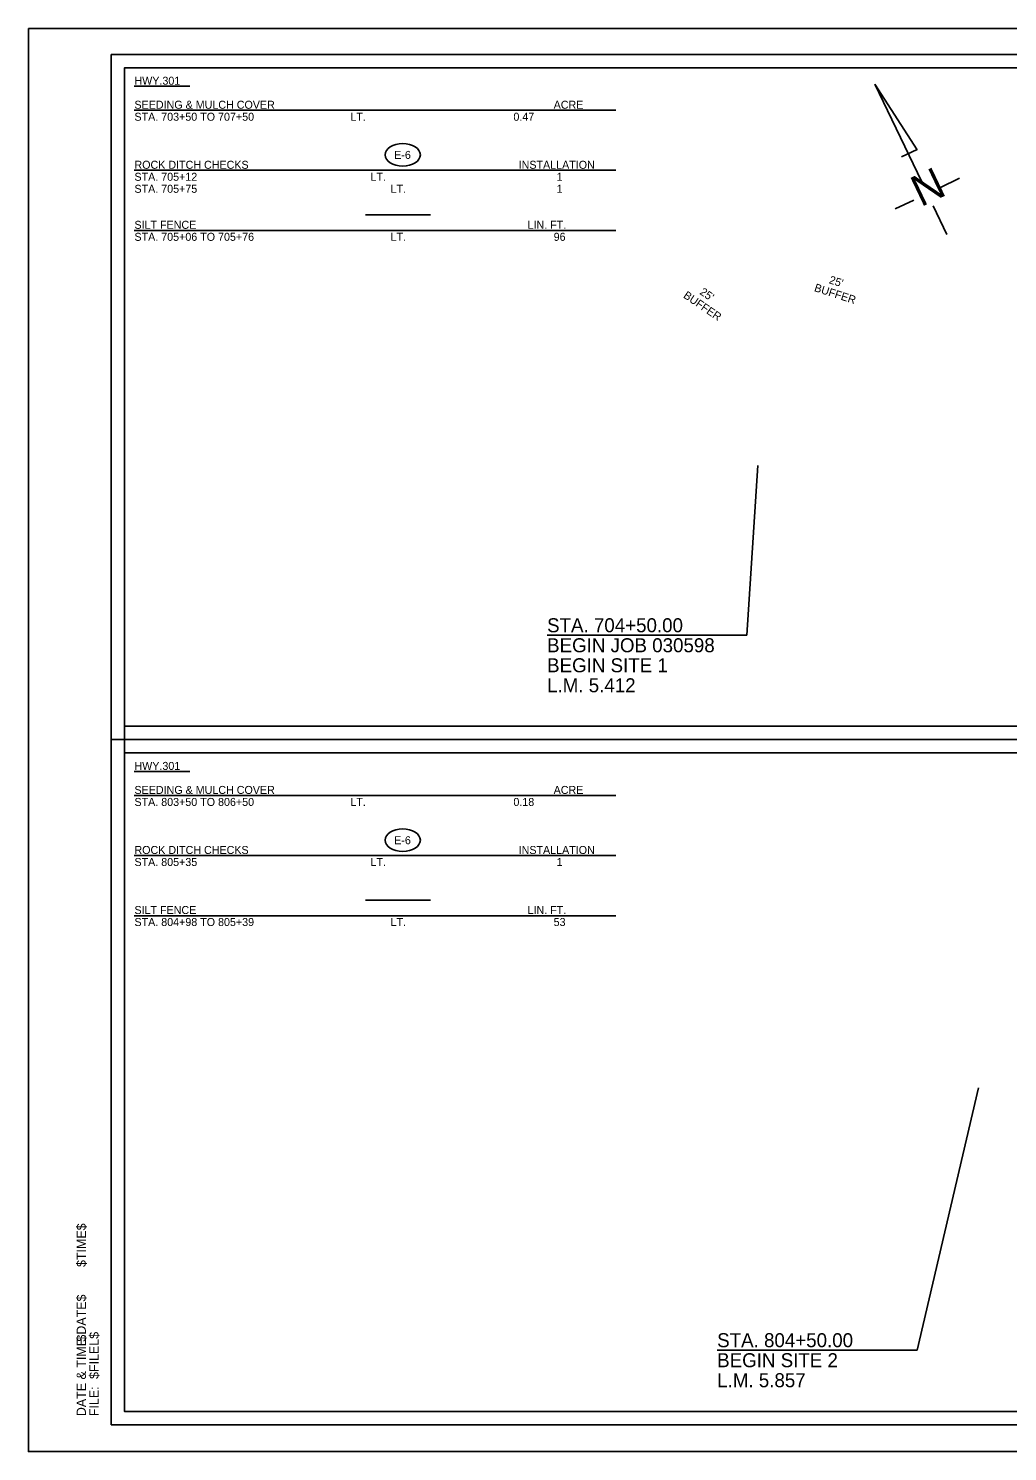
# Model space of a CAD drawing. Extents: x 814841 to 962585, y -174183 to 1802800.
# Drawn here: x 819050 to 819784, y 1801733 to 1802800 of the extents above; entities that cross this region are included whole.
import ezdxf

# ---------------------------------------------------------------- set-up
doc = ezdxf.new("R2010")
doc.units = 0
for name, color, linetype in [('Default', 7, 'Continuous'), ('Erosion Legend', 7, 'Continuous'), ('R_Border', 7, 'Continuous'), ('R_Border Notes', 7, 'Continuous'), ('R_Border Plan-Plan', 7, 'Continuous'), ('R_Detour Annot', 7, 'Continuous'), ('R_Draft', 7, 'Continuous'), ('R_No Plot', 7, 'Continuous'), ('Veg Buffer_Annot', 7, 'Continuous')]:
    doc.layers.add(name, color=color, linetype=linetype)

# ---------------------------------------------------------------- blocks, each defined once
blk = doc.blocks.new('E-6')
at = {"layer": 'Default'}
blk.add_ellipse((0, 0), major_axis=(13.2, 0), ratio=0.638788, dxfattribs=at)
blk.add_text('E-6', height=6, dxfattribs=at).set_placement((-6.4, -3))

msp = doc.modelspace()

# ---------------------------------------------------------------- linework, layer by layer
at = {"layer": 'Erosion Legend'}
for p, q in [((819129.1, 1802756.8), (819170.8, 1802756.8)), ((819129.1, 1802738.8), (819490.1, 1802738.8)), ((819129.1, 1802693.8), (819490.1, 1802693.8)), ((819302.3, 1802660.4), (819351.2, 1802660.4)), ((819129.1, 1802648.6), (819490.1, 1802648.6)), ((819129.1, 1802243.2), (819170.8, 1802243.2)), ((819129.1, 1802225.2), (819490.1, 1802225.2)), ((819129.1, 1802180.2), (819490.1, 1802180.2)), ((819302.3, 1802146.7), (819351.2, 1802146.7)), ((819129.1, 1802134.9), (819490.1, 1802134.9))]:
    msp.add_line(p, q, dxfattribs=at)
at = {"layer": 'R_Border'}
for p, q in [((819111.8, 1802780.6), (820692.7, 1802780.6)), ((819111.8, 1801753.3), (819111.8, 1802780.6)), ((819111.8, 1801753.3), (819111.8, 1801753.3)), ((820692.7, 1801753.3), (819111.8, 1801753.3))]:
    msp.add_line(p, q, dxfattribs=at)
at = {"layer": 'R_Border Plan-Plan'}
msp.add_line((819111.8, 1802267), (820692.7, 1802267), dxfattribs=at)
at = {"layer": 'R_Draft'}
for p, q in [((819684.3, 1802758.4), (819716, 1802709)), ((819719.4, 1802685), (819684.3, 1802758.4)), ((819704.1, 1802703.8), (819715.8, 1802709.4)), ((819732.8, 1802680.7), (819747.7, 1802687.8)), ((819699.4, 1802664.8), (819713.3, 1802671.4)), ((819738.2, 1802645.6), (819727.9, 1802667.2)), ((819588.2, 1802345.3), (819596.4, 1802472.5)), ((819588.2, 1802345.3), (819438.5, 1802345.3)), ((819716, 1801809.3), (819761.9, 1802006.1)), ((819716, 1801809.3), (819566, 1801809.3))]:
    msp.add_line(p, q, dxfattribs=at)
at = {"layer": 'R_No Plot'}
for points in [[(819049.7, 1802800.1), (820716.4, 1802800.1), (820716.4, 1801733.4), (819049.7, 1801733.4)], [(820682.7, 1802277), (819121.8, 1802277), (819121.8, 1802770.6), (820369.5, 1802770.6), (820369.5, 1802721.2), (820457.2, 1802721.2), (820577.7, 1802721.2), (820577.7, 1802609.5), (820682.7, 1802609.5)], [(820682.7, 1802277), (819121.8, 1802277), (819121.8, 1802770.6), (820369.5, 1802770.6), (820369.5, 1802721.2), (820457.2, 1802721.2), (820577.7, 1802721.2), (820577.7, 1802609.5), (820682.7, 1802609.5)], [(820682.7, 1802277), (819121.8, 1802277), (819121.8, 1802770.6), (820369.5, 1802770.6), (820369.5, 1802721.2), (820457.2, 1802721.2), (820577.7, 1802721.2), (820577.7, 1802609.5), (820682.7, 1802609.5)], [(820682.7, 1802277), (819121.8, 1802277), (819121.8, 1802770.6), (820369.5, 1802770.6), (820369.5, 1802721.2), (820457.2, 1802721.2), (820577.7, 1802721.2), (820577.7, 1802609.5), (820682.7, 1802609.5)], [(820682.7, 1802277), (819121.8, 1802277), (819121.8, 1802770.6), (820369.5, 1802770.6), (820369.5, 1802721.2), (820457.2, 1802721.2), (820577.7, 1802721.2), (820577.7, 1802609.5), (820682.7, 1802609.5)], [(820682.7, 1802277), (819121.8, 1802277), (819121.8, 1802770.6), (820369.5, 1802770.6), (820369.5, 1802721.2), (820457.2, 1802721.2), (820577.7, 1802721.2), (820577.7, 1802609.5), (820682.7, 1802609.5)], [(819121.8, 1802770.6), (820369.5, 1802770.6), (820369.5, 1802721.2), (820457.2, 1802721.2), (820577.7, 1802721.2), (820577.7, 1802609.5), (820682.7, 1802609.5), (820682.7, 1801763.3), (819121.8, 1801763.3)], [(820682.7, 1802277), (819121.8, 1802277), (819121.8, 1802770.6), (820369.5, 1802770.6), (820369.5, 1802721.2), (820457.2, 1802721.2), (820577.7, 1802721.2), (820577.7, 1802609.5), (820682.7, 1802609.5)], [(819121.8, 1802257), (820682.7, 1802257), (820682.7, 1801763.3), (819121.8, 1801763.3)], [(819121.8, 1802257), (820682.7, 1802257), (820682.7, 1801763.3), (819121.8, 1801763.3)], [(819121.8, 1802257), (820682.7, 1802257), (820682.7, 1801763.3), (819121.8, 1801763.3)], [(819121.8, 1802257), (820682.7, 1802257), (820682.7, 1801763.3), (819121.8, 1801763.3)], [(819121.8, 1802257), (820682.7, 1802257), (820682.7, 1801763.3), (819121.8, 1801763.3)], [(819121.8, 1802257), (820682.7, 1802257), (820682.7, 1801763.3), (819121.8, 1801763.3)], [(819121.8, 1802257), (820682.7, 1802257), (820682.7, 1801763.3), (819121.8, 1801763.3)]]:
    msp.add_lwpolyline(points, close=True, dxfattribs=at)

# ---------------------------------------------------------------- block references
at = {"layer": 'Erosion Legend', "rotation": -1.8065126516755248e-10}
for p in [(819330.3, 1802705.3), (819330.3, 1802191.6)]:
    msp.add_blockref('E-6', p, dxfattribs=at)

# ---------------------------------------------------------------- texts
at = {"layer": 'Erosion Legend'}
for s, p in [('HWY.301', (819129.2, 1802757.9)), ('SEEDING & MULCH COVER', (819129.2, 1802739.9)), (' ACRE', (819441.2, 1802739.9)), ('STA. 703+50 TO 707+50', (819129.2, 1802730.9)), ('        LT.    ', (819273.2, 1802730.9)), ('         0.47', (819393.2, 1802730.9)), ('ROCK DITCH CHECKS', (819129.2, 1802694.9)), ('INSTALLATION', (819417.2, 1802694.9)), ('STA. 705+12   ', (819129.2, 1802685.9)), ('STA. 705+75', (819129.2, 1802676.9)), ('    LT.', (819297.2, 1802685.9)), ('LT.', (819321.2, 1802676.9)), ('  1', (819441.2, 1802685.9)), ('  1', (819441.2, 1802676.9)), ('SILT FENCE', (819129.2, 1802649.9)), ('   LIN. FT.', (819417.2, 1802649.9)), ('STA. 705+06 TO 705+76', (819129.2, 1802640.9)), ('LT.', (819321.2, 1802640.9)), (' 96', (819441.2, 1802640.9)), ('HWY.301', (819129.2, 1802244.3)), ('SEEDING & MULCH COVER', (819129.2, 1802226.3)), ('STA. 803+50 TO 806+50', (819129.2, 1802217.3)), ('        LT.    ', (819273.2, 1802217.3)), ('         0.18', (819393.2, 1802217.3)), (' ACRE', (819441.2, 1802226.3)), ('ROCK DITCH CHECKS', (819129.2, 1802181.3)), ('INSTALLATION', (819417.2, 1802181.3)), ('STA. 805+35   ', (819129.2, 1802172.3)), ('    LT.', (819297.2, 1802172.3)), ('  1', (819441.2, 1802172.3)), ('SILT FENCE', (819129.2, 1802136.3)), ('   LIN. FT.', (819417.2, 1802136.3)), ('STA. 804+98 TO 805+39', (819129.2, 1802127.3)), ('LT.', (819321.2, 1802127.3)), (' 53', (819441.2, 1802127.3))]:
    msp.add_text(s, height=6, dxfattribs=at).set_placement(p)
at = {"layer": 'R_Border Notes'}
for s, height, p in [('$TIME$', 6.98, (819092.8, 1801871.7)), ('$DATE$', 6.98, (819092.8, 1801815.8)), ('DATE & TIME:', 6.984, (819092.8, 1801759.9)), ('$FILEL$', 6.98, (819102.4, 1801787.8)), ('FILE: ', 6.98, (819102.4, 1801759.9))]:
    msp.add_text(s, height=height, rotation=90, dxfattribs=at).set_placement(p)
at = {"layer": 'R_Detour Annot'}
for s, p in [('STA. 704+50.00', (819438.5, 1802347.5)), ('BEGIN JOB 030598 ', (819438.5, 1802332.5)), ('BEGIN SITE 1', (819438.5, 1802317.5)), ('L.M. 5.412', (819438.5, 1802302.5)), ('STA. 804+50.00 ', (819566, 1801811.6)), ('BEGIN SITE 2', (819566, 1801796.6)), ('L.M. 5.857', (819566, 1801781.6))]:
    msp.add_text(s, height=10.5, dxfattribs=at).set_placement(p)
at = {"layer": 'R_Draft'}
msp.add_text('N', height=23.3, rotation=25.5319, dxfattribs=at).set_placement((819718.7, 1802666))
at = {"layer": 'Veg Buffer_Annot'}
for s, rotation, p in [('BUFFER', 342.1183, (819638.3, 1802603.3)), ("25'", 342.1183, (819649.4, 1802609.2)), ('BUFFER', 325.6564, (819540.1, 1802598.7)), ("25'", 325.6564, (819552.4, 1802601.3))]:
    msp.add_text(s, height=6, rotation=rotation, dxfattribs=at).set_placement(p)

doc.saveas('drawing.dxf')
